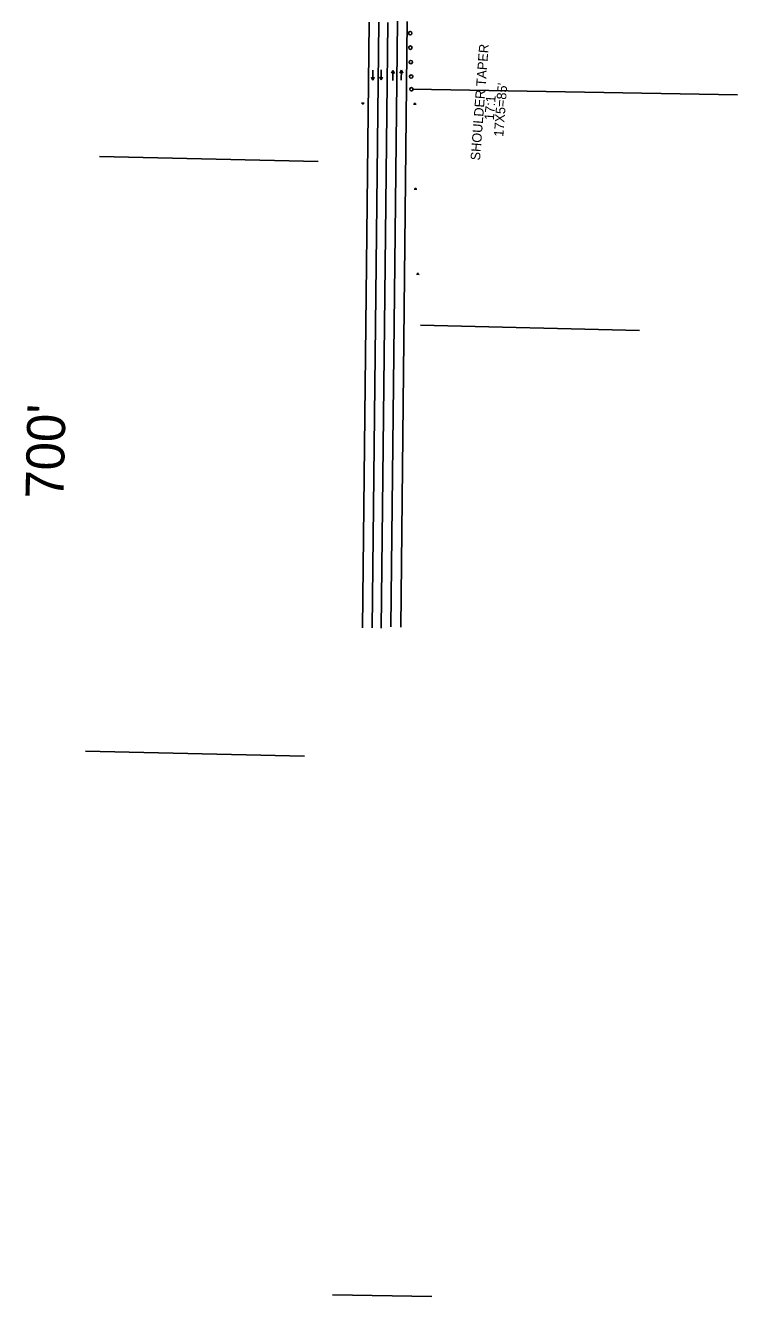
# Model space of a CAD drawing. Extents: x 1650647 to 1653016, y 602856 to 611467.
# Drawn here: x 1652071 to 1652908, y 602856 to 604352 of the extents above; entities that cross this region are included whole.
import ezdxf

# ---------------------------------------------------------------- set-up
doc = ezdxf.new("R2010")
doc.units = 0
for name, color, linetype in [('CM_Corridor_Design', 7, 'Continuous'), ('DT_X_Break_Line', 7, 'Continuous'), ('PF_P_Grade_Line', 7, 'Continuous'), ('PF_X_Ground_Line', 7, 'Continuous'), ('PF_X_Ground_Line_RT', 7, 'Continuous'), ('PV_P_Curb', 7, 'Continuous'), ('SC_Scratch1', 7, 'Continuous'), ('UT_X_Water', 7, 'Continuous')]:
    doc.layers.add(name, color=color, linetype=linetype)

msp = doc.modelspace()

# ---------------------------------------------------------------- linework, layer by layer
at = {"layer": 'CM_Corridor_Design'}
for p, q in [((1652479.2, 604287.3), (1652479.4, 604299.2)), ((1652489.1, 604287.7), (1652489.2, 604299.5)), ((1652503, 604298.7), (1652501.3, 604295.4)), ((1652503, 604298.7), (1652502.9, 604286.9)), ((1652503, 604298.7), (1652504.7, 604295.3)), ((1652512.9, 604299.1), (1652511.1, 604295.7)), ((1652512.9, 604299.1), (1652512.7, 604287.2)), ((1652512.9, 604299.1), (1652514.6, 604295.7)), ((1652479.2, 604287.3), (1652477.6, 604290.7)), ((1652479.2, 604287.3), (1652481, 604290.7)), ((1652489.1, 604287.7), (1652487.4, 604291.1)), ((1652489.1, 604287.7), (1652490.8, 604291))]:
    msp.add_line(p, q, dxfattribs=at)
at = {"layer": 'DT_X_Break_Line'}
for centre in [(1652523.3, 604342.6), (1652523.6, 604325.6), (1652524, 604308.6), (1652524.4, 604291.6), (1652524.7, 604276.6)]:
    msp.add_circle(centre, 2, dxfattribs=at)
at = {"layer": 'PF_P_Grade_Line'}
for p, q in [((1652508.4, 604356.6), (1652500.6, 603644)), ((1652486.4, 604355.4), (1652478.6, 603642.8))]:
    msp.add_line(p, q, dxfattribs=at)
at = {"layer": 'PF_X_Ground_Line'}
for p, q in [((1652469.1, 604260.3), (1652465.9, 604260.4)), ((1652467.5, 604260.3), (1652467.4, 604258.7)), ((1652467.5, 604260.3), (1652467.5, 604260.3)), ((1652530.4, 604259), (1652527.2, 604259.1)), ((1652528.8, 604259.1), (1652528.8, 604260.7)), ((1652528.8, 604259.1), (1652528.8, 604259.1)), ((1652531.1, 604159), (1652527.9, 604159.1)), ((1652529.5, 604159), (1652529.6, 604160.6)), ((1652529.5, 604159), (1652529.5, 604159)), ((1652533.8, 604058.8), (1652530.6, 604058.9)), ((1652532.2, 604058.9), (1652532.2, 604060.5)), ((1652532.2, 604058.9), (1652532.2, 604058.9))]:
    msp.add_line(p, q, dxfattribs=at)
at = {"layer": 'PF_X_Ground_Line_RT'}
for p, q in [((1652526, 604276.7), (1652908.4, 604270.1)), ((1652431.9, 602858.1), (1652548.9, 602856.1))]:
    msp.add_line(p, q, dxfattribs=at)
at = {"layer": 'PV_P_Curb'}
msp.add_line((1652496.9, 604355.3), (1652489.1, 603642.7), dxfattribs=at)
at = {"layer": 'SC_Scratch1'}
for p, q in [((1652519.9, 604356.4), (1652512.1, 603643.8)), ((1652474.9, 604355.7), (1652467.1, 603643.1))]:
    msp.add_line(p, q, dxfattribs=at)
at = {"layer": 'UT_X_Water'}
for p, q in [((1652415.2, 604191.7), (1652157.7, 604197.7)), ((1652793, 603992.9), (1652535.6, 603998.9)), ((1652399, 603491.9), (1652141.5, 603497.9))]:
    msp.add_line(p, q, dxfattribs=at)

# ---------------------------------------------------------------- texts
at = {"layer": 'PF_X_Ground_Line_RT'}
for s, p in [('SHOULDER TAPER', (1652605.4, 604192.6)), ("17X5=85'", (1652632.8, 604220.5)), ('17:1', (1652621.7, 604239.9))]:
    msp.add_text(s, height=11.2, rotation=85.6823, dxfattribs=at).set_placement(p)
at = {"layer": 'UT_X_Water'}
msp.add_text("700'", height=44.8, rotation=88.672, dxfattribs=at).set_placement((1652115.4, 603794.4))

doc.saveas('drawing.dxf')
